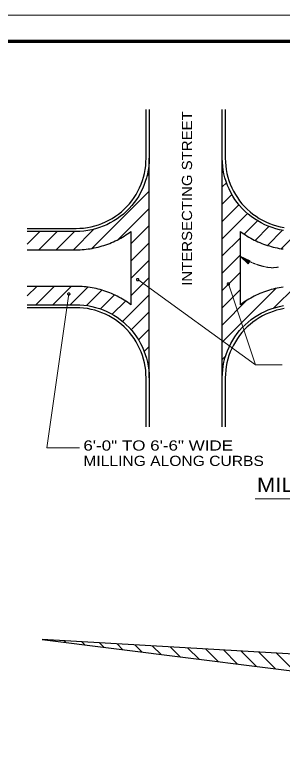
# Model space of a CAD drawing. Extents: x 44.6 to 61.6, y -38.7 to -27.7.
# Drawn here: x 48.14 to 50.34, y -33.85 to -27.69 of the extents above; entities that cross this region are included whole.
import ezdxf

# ---------------------------------------------------------------- set-up
doc = ezdxf.new("R2010")
doc.units = 0
doc.header["$LTSCALE"] = 0.025
for name, color, linetype, lineweight in [('6', 7, 'Continuous', 13), ('60', 7, 'Continuous', 13), ('8', 7, 'Continuous', 13), ('9', 7, 'Continuous', 13)]:
    doc.layers.add(name, color=color, linetype=linetype, lineweight=lineweight)

msp = doc.modelspace()

# ---------------------------------------------------------------- linework, layer by layer
at = {"layer": '6', "lineweight": 25}
for p, q in [((49.24203, -30.66542), (49.24203, -28.86542)), ((49.84203, -30.66542), (49.84203, -28.86542)), ((49.86889, -30.48794), (49.84203, -30.51478)), ((49.24203, -30.54909), (49.23246, -30.55867))]:
    msp.add_line(p, q, dxfattribs=at)
at = {"layer": '6'}
for p, q in [((49.84203, -28.95915), (49.84843, -28.95276)), ((49.22397, -29.01152), (49.24203, -28.99346)), ((49.87657, -29.06603), (49.84203, -29.10057)), ((49.24203, -29.13489), (48.77303, -29.60389)), ((49.84203, -29.24199), (49.92103, -29.163)), ((49.97875, -29.24669), (49.84203, -29.38342)), ((48.98694, -29.53141), (49.24203, -29.2763)), ((49.84203, -29.52483), (50.04852, -29.31834)), ((50.13025, -29.37804), (50.02172, -29.48657)), ((48.62008, -29.61542), (48.78815, -29.44735)), ((49.24203, -29.41773), (49.09203, -29.56773)), ((50.11121, -29.53851), (50.22495, -29.42476)), ((48.34582, -29.46542), (48.24203, -29.5692)), ((48.33724, -29.61542), (48.48724, -29.46542)), ((48.62866, -29.46542), (48.47866, -29.61542)), ((50.33529, -29.45584), (50.2119, -29.57923)), ((50.32615, -29.60641), (50.46714, -29.46542)), ((49.09203, -29.70915), (49.24203, -29.55915)), ((49.99203, -29.51625), (49.84203, -29.66625)), ((49.84203, -29.80768), (49.99203, -29.65768)), ((49.24203, -29.70057), (49.09203, -29.85057)), ((49.99203, -29.79909), (49.84203, -29.94909)), ((49.09203, -29.99199), (49.24203, -29.84199)), ((48.24203, -29.99346), (48.32008, -29.91542)), ((48.4615, -29.91542), (48.3115, -30.06542)), ((48.45293, -30.06542), (48.60293, -29.91542)), ((48.73816, -29.9216), (48.59434, -30.06542)), ((49.84203, -30.37336), (50.28291, -29.93249)), ((49.84203, -30.09052), (49.99203, -29.94052)), ((50.11343, -30.55702), (49.89279, -29.89514)), ((50.44172, -29.91509), (50.26455, -30.09226)), ((48.72937, -30.0718), (48.85492, -29.94626)), ((48.95758, -29.98502), (48.84266, -30.09995)), ((49.24203, -29.98342), (49.02331, -30.20214)), ((48.93961, -30.14441), (49.04875, -30.03527)), ((50.04459, -30.02937), (49.84203, -30.23194)), ((49.09497, -30.27191), (49.24203, -30.12483)), ((49.24203, -30.26625), (49.15467, -30.35362)), ((49.20139, -30.44832), (49.24203, -30.40768)), ((48.54355, -32.81947), (48.55741, -32.83334)), ((48.7137, -32.85351), (48.68976, -32.8283)), ((48.8347, -32.83711), (48.86999, -32.87241)), ((49.02755, -32.89257), (48.97966, -32.84468)), ((49.12459, -32.85351), (49.18384, -32.91149)), ((49.34014, -32.93166), (49.2708, -32.86232)), ((49.41576, -32.86989), (49.49643, -32.95055)), ((49.65272, -32.97072), (49.5607, -32.87872)), ((49.70566, -32.88628), (49.80901, -32.98964)), ((49.9653, -33.0098), (49.85186, -32.89509)), ((49.9968, -32.90393), (50.12159, -33.0287)), ((50.27914, -33.04886), (50.14176, -32.91149)), ((50.2867, -32.9203), (50.43543, -33.06778))]:
    msp.add_line(p, q, dxfattribs=at)
at = {"layer": '6', "lineweight": 25}
for points in [[(49.24203, -28.46542), (49.24203, -28.86542), (49.24116, -28.8979), (49.23852, -28.93028), (49.23412, -28.96248), (49.22801, -28.9944), (49.22017, -29.02594), (49.21063, -29.057), (49.19942, -29.0875), (49.18658, -29.11735), (49.17214, -29.14646), (49.15615, -29.17475), (49.13865, -29.20212), (49.11969, -29.22852), (49.09933, -29.25384), (49.07762, -29.27803), (49.05466, -29.30101), (49.03047, -29.32272), (49.00514, -29.34307), (48.97874, -29.36203), (48.95136, -29.37953), (48.92307, -29.39552), (48.89397, -29.40996), (48.86411, -29.4228), (48.83361, -29.43401), (48.80255, -29.44354), (48.77101, -29.45139), (48.7391, -29.45751), (48.70691, -29.4619), (48.67451, -29.46454), (48.64203, -29.46542), (48.24203, -29.46542)], [(48.24203, -29.44042), (48.64203, -29.44042), (48.67317, -29.43957), (48.7042, -29.43704), (48.73506, -29.43284), (48.76565, -29.42697), (48.79586, -29.41946), (48.82564, -29.41031), (48.85486, -29.39957), (48.88347, -29.38727), (48.91136, -29.37344), (48.93848, -29.3581), (48.96472, -29.34133), (48.99001, -29.32317), (49.01428, -29.30366), (49.03746, -29.28286), (49.05948, -29.26084), (49.08027, -29.23767), (49.09978, -29.21339), (49.11795, -29.18809), (49.13472, -29.16185), (49.15005, -29.13475), (49.16389, -29.10685), (49.17619, -29.07825), (49.18693, -29.04901), (49.19607, -29.01925), (49.20358, -28.98902), (49.20946, -28.95844), (49.21366, -28.92758), (49.21619, -28.89654), (49.21703, -28.86542), (49.21703, -28.86542), (49.21703, -28.46542)], [(50.34497, -29.45751), (50.31305, -29.45139), (50.28152, -29.44354), (50.25045, -29.43401), (50.21995, -29.4228), (50.1901, -29.40996), (50.16099, -29.39552), (50.1327, -29.37953), (50.10532, -29.36203), (50.07893, -29.34307), (50.0536, -29.32271), (50.02942, -29.30101), (50.00644, -29.27803), (49.98474, -29.25384), (49.96437, -29.22852), (49.94542, -29.20212), (49.92792, -29.17475), (49.91193, -29.14646), (49.89749, -29.11735), (49.88465, -29.0875), (49.87344, -29.057), (49.86391, -29.02594), (49.85606, -28.9944), (49.84994, -28.96249), (49.84555, -28.93029), (49.84291, -28.8979), (49.84203, -28.86542), (49.84203, -28.86542), (49.84203, -28.46542)], [(49.86703, -28.46542), (49.86703, -28.86542), (49.86787, -28.89654), (49.87041, -28.92758), (49.8746, -28.95844), (49.88048, -28.98902), (49.88799, -29.01924), (49.89714, -29.04901), (49.90787, -29.07824), (49.92018, -29.10685), (49.93401, -29.13475), (49.94934, -29.16185), (49.96611, -29.18809), (49.98428, -29.21339), (50.00379, -29.23767), (50.02458, -29.26084), (50.0466, -29.28286), (50.06978, -29.30366), (50.09405, -29.32317), (50.11934, -29.34133), (50.14558, -29.3581), (50.1727, -29.37344), (50.20059, -29.38727), (50.2292, -29.39957), (50.25844, -29.41031), (50.2882, -29.41946), (50.31843, -29.42697), (50.34901, -29.43284)], [(48.24203, -29.61542), (48.64203, -29.61542), (48.65868, -29.61523), (48.6753, -29.61468), (48.69193, -29.61375), (48.70851, -29.61246), (48.72507, -29.6108), (48.74159, -29.60878), (48.75806, -29.60639), (48.77447, -29.60362), (48.79082, -29.60051), (48.80709, -29.59703), (48.82328, -29.59319), (48.83939, -29.58898), (48.8554, -29.58443), (48.87129, -29.57951), (48.88708, -29.57425), (48.90275, -29.56865), (48.91829, -29.56269), (48.93369, -29.55639), (48.94895, -29.54974), (48.96406, -29.54276), (48.97901, -29.53545), (48.99379, -29.52781), (49.00841, -29.51984), (49.02283, -29.51155), (49.03707, -29.50295), (49.05112, -29.49402), (49.06497, -29.48479), (49.0786, -29.47525), (49.09203, -29.46542), (49.09203, -30.06542), (49.07861, -30.05557), (49.06497, -30.04604), (49.05112, -30.03681), (49.03707, -30.02789), (49.02283, -30.01928), (49.00841, -30.01099), (48.99379, -30.00302), (48.97901, -29.99537), (48.96406, -29.98807), (48.94895, -29.98109), (48.93369, -29.97445), (48.91829, -29.96815), (48.90275, -29.96219), (48.88708, -29.95657), (48.87129, -29.95131), (48.8554, -29.94641), (48.83939, -29.94184), (48.82328, -29.93765), (48.80709, -29.9338), (48.79082, -29.93032), (48.77447, -29.9272), (48.75806, -29.92445), (48.74159, -29.92205), (48.72507, -29.92003), (48.70851, -29.91836), (48.69192, -29.91707), (48.6753, -29.91616), (48.65867, -29.9156), (48.64203, -29.91542), (48.64203, -29.91542), (48.24203, -29.91542)], [(49.99203, -29.46542), (50.00546, -29.47525), (50.01909, -29.48479), (50.03294, -29.49402), (50.04699, -29.50294), (50.06123, -29.51155), (50.07567, -29.51984), (50.09027, -29.52781), (50.10505, -29.53545), (50.12001, -29.54276), (50.13511, -29.54974), (50.15037, -29.55639), (50.16577, -29.56269), (50.18131, -29.56865), (50.19698, -29.57425), (50.21277, -29.57951), (50.22867, -29.58443), (50.24468, -29.58898), (50.26078, -29.59319), (50.27697, -29.59703), (50.29324, -29.60051), (50.30959, -29.60362), (50.326, -29.60639), (50.34247, -29.60878)], [(50.29325, -29.93032), (50.27697, -29.9338), (50.26078, -29.93765), (50.24468, -29.94184), (50.22867, -29.94641), (50.21277, -29.95131), (50.19698, -29.95657), (50.18131, -29.96219), (50.16577, -29.96815), (50.15037, -29.97445), (50.13511, -29.98109), (50.12, -29.98807), (50.10505, -29.99539), (50.09027, -30.00302), (50.07566, -30.01099), (50.06123, -30.01928), (50.04699, -30.02789), (50.03294, -30.03681), (50.01909, -30.04604), (50.00546, -30.05558), (49.99203, -30.06542), (49.99203, -29.46542)], [(50.34247, -29.92205), (50.326, -29.92445), (50.30959, -29.9272), (50.29325, -29.93032)], [(48.24203, -30.06542), (48.64203, -30.06542), (48.67452, -30.06629), (48.70691, -30.06893), (48.7391, -30.07332), (48.77101, -30.07945), (48.80255, -30.08728), (48.83361, -30.09682), (48.86411, -30.10803), (48.89397, -30.12087), (48.92307, -30.13531), (48.95136, -30.1513), (48.97875, -30.1688), (49.00514, -30.18776), (49.03047, -30.20811), (49.05466, -30.22982), (49.07762, -30.25279), (49.09933, -30.27699), (49.11969, -30.30231), (49.13865, -30.32871), (49.15615, -30.35608), (49.17214, -30.38437), (49.18657, -30.41348), (49.19942, -30.44333), (49.21063, -30.47383), (49.22016, -30.5049), (49.228, -30.53644), (49.23412, -30.56834), (49.23851, -30.60054), (49.24115, -30.63294), (49.24203, -30.66542), (49.24203, -30.66542), (49.24203, -31.06542)], [(49.21703, -31.06542), (49.21703, -30.66542), (49.21619, -30.63428), (49.21367, -30.60325), (49.20946, -30.57239), (49.20359, -30.5418), (49.19607, -30.51158), (49.18694, -30.48181), (49.1762, -30.45258), (49.16389, -30.42398), (49.15005, -30.39608), (49.13473, -30.36897), (49.11795, -30.34273), (49.09978, -30.31744), (49.08027, -30.29317), (49.05948, -30.26999), (49.03746, -30.24797), (49.01428, -30.22718), (48.99001, -30.20767), (48.96472, -30.18949), (48.93848, -30.17272), (48.91136, -30.1574), (48.88347, -30.14356), (48.85486, -30.13125), (48.82562, -30.12051), (48.79586, -30.11137), (48.76564, -30.10386), (48.73505, -30.09799), (48.7042, -30.09379), (48.67316, -30.09126), (48.64203, -30.09042), (48.64203, -30.09042), (48.24203, -30.09042)], [(49.84203, -31.06542), (49.84203, -30.66542), (49.84292, -30.63293), (49.84555, -30.60054), (49.84994, -30.56834), (49.85606, -30.53644), (49.86391, -30.5049), (49.87344, -30.47383), (49.88465, -30.44333), (49.89749, -30.41348), (49.91193, -30.38437), (49.92792, -30.35608), (49.94542, -30.32871), (49.96437, -30.30231), (49.98474, -30.27699), (50.00644, -30.25279), (50.02942, -30.22982), (50.0536, -30.20811), (50.07893, -30.18776), (50.10532, -30.1688), (50.1327, -30.1513), (50.16099, -30.13531), (50.19009, -30.12087), (50.21995, -30.10803), (50.25045, -30.09682), (50.28151, -30.08729), (50.31305, -30.07945), (50.34496, -30.07332)], [(50.34901, -30.09799), (50.31843, -30.10385), (50.28821, -30.11137), (50.25844, -30.12051), (50.2292, -30.13125), (50.20059, -30.14356), (50.1727, -30.1574), (50.14558, -30.17272), (50.11935, -30.18949), (50.09405, -30.20766), (50.06978, -30.22717), (50.0466, -30.24797), (50.02458, -30.26999), (50.00379, -30.29317), (49.98428, -30.31744), (49.96611, -30.34273), (49.94933, -30.36897), (49.93401, -30.39608), (49.92018, -30.42398), (49.90786, -30.45258), (49.89712, -30.48181), (49.88799, -30.51158), (49.88047, -30.54181), (49.8746, -30.5724), (49.87041, -30.60325), (49.86787, -30.63429), (49.86703, -30.66542), (49.86703, -30.66542), (49.86703, -31.06542)]]:
    msp.add_lwpolyline(points, dxfattribs=at)
at = {"layer": '6'}
for points in [[(50.04346, -29.70033), (50.03992, -29.69844), (50.03637, -29.69651), (50.03285, -29.69456), (50.02935, -29.69259), (50.02585, -29.69059), (50.02237, -29.68858), (50.01891, -29.68653), (50.01546, -29.68447), (50.01202, -29.68238), (50.00859, -29.68026), (50.00519, -29.67812), (50.00179, -29.67596), (49.99842, -29.67378), (49.99505, -29.67157), (49.9917, -29.66933), (49.98836, -29.66708)], [(50.30396, -29.75709), (50.30223, -29.75744), (50.30049, -29.75777), (50.29875, -29.75808), (50.29701, -29.7584), (50.29526, -29.7587), (50.29352, -29.75898), (50.29177, -29.75925), (50.29002, -29.75951), (50.28827, -29.75976), (50.28652, -29.76), (50.28476, -29.76022), (50.28301, -29.76044), (50.28125, -29.76064), (50.27949, -29.76082), (50.27773, -29.761), (50.27597, -29.76116), (50.27421, -29.76131), (50.27244, -29.76145), (50.27068, -29.76158), (50.26892, -29.7617), (50.26715, -29.7618), (50.26537, -29.76189), (50.26361, -29.76197), (50.26184, -29.76203), (50.26007, -29.76209), (50.25831, -29.76214), (50.25654, -29.76217), (50.25477, -29.76218), (50.253, -29.76219), (50.25123, -29.76218), (50.24946, -29.76217), (50.2477, -29.76214), (50.24593, -29.76209), (50.24416, -29.76203), (50.24239, -29.76197), (50.24063, -29.76189), (50.23885, -29.7618), (50.23709, -29.7617), (50.23532, -29.76158), (50.23356, -29.76145), (50.2318, -29.76131), (50.23003, -29.76116), (50.22827, -29.761), (50.22651, -29.76082), (50.22475, -29.76064), (50.223, -29.76044), (50.22124, -29.76022), (50.21949, -29.76), (50.21773, -29.75976), (50.21598, -29.75951), (50.21423, -29.75925), (50.21248, -29.75898), (50.21074, -29.7587), (50.20899, -29.7584), (50.20725, -29.75808), (50.20551, -29.75777), (50.20377, -29.75744), (50.20204, -29.75709), (50.19809, -29.75628), (50.19416, -29.75545), (50.19023, -29.75458), (50.1863, -29.75369), (50.18239, -29.75277), (50.17848, -29.75182), (50.17457, -29.75085), (50.17068, -29.74985), (50.16678, -29.74882), (50.1629, -29.74777), (50.15902, -29.7467), (50.15516, -29.74558), (50.15129, -29.74446), (50.14744, -29.7433), (50.14359, -29.74211), (50.13976, -29.7409), (50.13593, -29.73967), (50.1321, -29.7384), (50.12829, -29.7371), (50.12449, -29.73579), (50.1207, -29.73445), (50.11692, -29.73307), (50.11314, -29.73169), (50.10938, -29.73026), (50.10562, -29.72881), (50.10187, -29.72734), (50.09814, -29.72584), (50.09442, -29.72432), (50.0907, -29.72277), (50.087, -29.7212), (50.0833, -29.71959), (50.07963, -29.71797), (50.07596, -29.71632), (50.0723, -29.71465), (50.06865, -29.71294), (50.06501, -29.71122), (50.0614, -29.70947), (50.05778, -29.70769), (50.05419, -29.70589), (50.05059, -29.70406), (50.04702, -29.70221), (50.04346, -29.70033)], [(50.33242, -30.55702), (50.11343, -30.55702), (49.14821, -29.86033)], [(48.67093, -31.23939), (48.40364, -31.23939), (48.58292, -29.97781)]]:
    msp.add_lwpolyline(points, dxfattribs=at)
for points in [[(49.1401, -29.85448), (49.13951, -29.8554), (49.13903, -29.85636), (49.13866, -29.85737), (49.1384, -29.85843), (49.13824, -29.8595), (49.13821, -29.86058), (49.13829, -29.86166), (49.1385, -29.86273), (49.13881, -29.86376), (49.13924, -29.86476), (49.13977, -29.8657), (49.1404, -29.86658), (49.14112, -29.86739), (49.14193, -29.86811), (49.1428, -29.86875), (49.14374, -29.86928), (49.14474, -29.86971), (49.14577, -29.87003), (49.14683, -29.87024), (49.14792, -29.87033), (49.149, -29.8703), (49.15007, -29.87016), (49.15113, -29.8699), (49.15214, -29.86953), (49.1531, -29.86905), (49.15402, -29.86847), (49.15486, -29.86779), (49.15564, -29.86703), (49.15631, -29.86619), (49.15631, -29.86619), (49.15691, -29.86527), (49.15739, -29.8643), (49.15776, -29.86329), (49.15802, -29.86224), (49.15818, -29.86117), (49.15821, -29.86008), (49.15811, -29.85901), (49.15792, -29.85794), (49.1576, -29.85691), (49.15718, -29.85591), (49.15665, -29.85497), (49.15602, -29.85408), (49.15529, -29.85328), (49.15449, -29.85255), (49.15361, -29.85192), (49.15267, -29.85139), (49.15168, -29.85096), (49.15065, -29.85064), (49.14958, -29.85043), (49.1485, -29.85033), (49.14742, -29.85036), (49.14634, -29.85051), (49.14529, -29.85077), (49.14428, -29.85114), (49.1433, -29.85161), (49.1424, -29.8522), (49.14154, -29.85287), (49.14078, -29.85364), (49.1401, -29.85448)], [(49.88962, -29.88565), (49.88862, -29.88604), (49.88767, -29.88655), (49.88676, -29.88716), (49.88594, -29.88785), (49.88519, -29.88864), (49.88453, -29.8895), (49.88397, -29.89043), (49.88351, -29.89141), (49.88317, -29.89243), (49.88293, -29.89349), (49.88281, -29.89456), (49.8828, -29.89565), (49.88292, -29.89672), (49.88315, -29.89778), (49.88349, -29.8988), (49.88394, -29.89979), (49.8845, -29.90072), (49.88515, -29.90158), (49.88589, -29.90237), (49.88671, -29.90307), (49.8876, -29.90369), (49.88856, -29.9042), (49.88956, -29.9046), (49.89061, -29.9049), (49.89168, -29.90507), (49.89276, -29.90514), (49.89384, -29.90508), (49.89491, -29.90491), (49.89596, -29.90462), (49.89596, -29.90462), (49.89696, -29.90423), (49.89792, -29.90372), (49.89881, -29.90311), (49.89965, -29.90242), (49.9004, -29.90164), (49.90105, -29.90077), (49.90161, -29.89984), (49.90207, -29.89886), (49.90242, -29.89784), (49.90266, -29.89678), (49.90277, -29.89571), (49.90278, -29.89462), (49.90267, -29.89355), (49.90244, -29.89249), (49.90209, -29.89147), (49.90165, -29.89048), (49.90108, -29.88955), (49.90044, -29.88869), (49.89969, -29.8879), (49.89886, -29.8872), (49.89798, -29.88658), (49.89702, -29.88607), (49.89601, -29.88567), (49.89497, -29.88537), (49.89391, -29.8852), (49.89282, -29.88514), (49.89174, -29.88519), (49.89068, -29.88536), (49.88962, -29.88565)], [(48.58432, -29.96792), (48.58324, -29.96782), (48.58217, -29.96784), (48.58108, -29.96798), (48.58003, -29.96824), (48.57902, -29.9686), (48.57804, -29.96908), (48.57712, -29.96966), (48.57628, -29.97033), (48.57551, -29.97109), (48.57482, -29.97193), (48.57424, -29.97284), (48.57375, -29.97381), (48.57337, -29.97482), (48.5731, -29.97587), (48.57296, -29.97695), (48.57292, -29.97802), (48.573, -29.9791), (48.5732, -29.98017), (48.57351, -29.98121), (48.57393, -29.98221), (48.57446, -29.98315), (48.57508, -29.98403), (48.5758, -29.98484), (48.5766, -29.98557), (48.57748, -29.98621), (48.57842, -29.98675), (48.57942, -29.98718), (48.58045, -29.9875), (48.58151, -29.98771), (48.58151, -29.98771), (48.58258, -29.9878), (48.58367, -29.98778), (48.58474, -29.98765), (48.58579, -29.98739), (48.58681, -29.98702), (48.58779, -29.98654), (48.5887, -29.98597), (48.58955, -29.98529), (48.59032, -29.98453), (48.591, -29.9837), (48.59159, -29.98278), (48.59208, -29.98181), (48.59246, -29.9808), (48.59273, -29.97975), (48.59287, -29.97868), (48.59292, -29.9776), (48.59283, -29.97652), (48.59264, -29.97546), (48.59232, -29.97442), (48.5919, -29.97342), (48.59137, -29.97248), (48.59075, -29.97159), (48.59003, -29.97078), (48.58923, -29.97005), (48.58835, -29.96942), (48.58741, -29.96888), (48.58642, -29.96845), (48.58539, -29.96813), (48.58432, -29.96792)]]:
    msp.add_lwpolyline(points, close=True, dxfattribs=at)
at = {"layer": '6', "lineweight": 25}
msp.add_lwpolyline([(51.37066, -32.98332), (48.36457, -32.80939), (51.37066, -33.18499)], close=True, dxfattribs=at)
at = {"layer": '60'}
msp.add_lwpolyline([(61.57033, -38.69864), (44.55984, -38.69864), (44.55984, -27.69184), (61.57033, -27.69184)], close=True, dxfattribs=at)
at = {"layer": '60', "lineweight": 70}
msp.add_lwpolyline([(60.8892, -27.90872), (44.82119, -27.90872), (44.82119, -38.46427), (60.8892, -38.46427)], close=True, dxfattribs=at)
at = {"layer": '8'}
msp.add_line((50.11106, -31.65631), (52.67071, -31.65631), dxfattribs=at)
at = {"layer": '9'}
for points in [[(50.06915, -29.71104), (49.98836, -29.66708), (50.06399, -29.7186), (50.06142, -29.72239), (49.98836, -29.66708), (50.05884, -29.72617), (50.06656, -29.71482), (49.99216, -29.66967)], [(49.98907, -29.66685), (50.07176, -29.70733), (50.0558, -29.73075), (49.98864, -29.66694)]]:
    msp.add_lwpolyline(points, dxfattribs=at)

# ---------------------------------------------------------------- texts
at = {"layer": '6', "width": 1.1}
msp.add_text('INTERSECTING STREET', height=0.08333, rotation=90, dxfattribs=at).set_placement((49.59423, -29.91069))
at = {"layer": '6'}
for s, width, p in [('6\'-0" TO 6\'-6" WIDE', 1.25, (48.70243, -31.26101)), ('MILLING ALONG CURBS', 1.15, (48.70243, -31.387))]:
    msp.add_text(s, height=0.08333, dxfattribs=dict(at, width=width)).set_placement(p)
at = {"layer": '8', "width": 1.15}
msp.add_text('MILLING AT INTERSECTIONS', height=0.1175, dxfattribs=at).set_placement((50.12656, -31.59983))

doc.saveas('drawing.dxf')
